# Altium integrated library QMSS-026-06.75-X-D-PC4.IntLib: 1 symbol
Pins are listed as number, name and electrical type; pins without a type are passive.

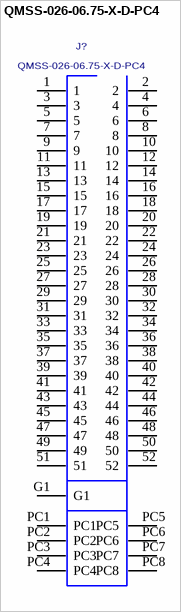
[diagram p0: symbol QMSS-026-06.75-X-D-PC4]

## QMSS-026-06.75-X-D-PC4
designator J?
HIGH SPEED SHIELDED TERMINAL, .025" (.635mm) PITCH.; MANUFACTURER: SAMTEC
footprint QMSS-026-06.75-X-D-PC4
pins: 1, 2, 3, 4, 5, 6, 7, 8, 9, 10, 11, 12, 13, 14, 15, 16, 17, 18, 19, 20, 21, 22, 23, 24, 25, 26, 27, 28, 29, 30, 31, 32, 33, 34, 35, 36, 37, 38, 39, 40, 41, 42, 43, 44, 45, 46, 47, 48, 49, 50, 51, 52, G1, PC1, PC2, PC3, PC4, PC5, PC6, PC7, PC8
